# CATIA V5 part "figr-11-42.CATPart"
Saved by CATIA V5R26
Part number: Part1
Bounding box of the stored display mesh (mm): x -82.6 to 82.6, y -78 to 78, z 0 to 136
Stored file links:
  D:\_Deepak\CATIA\CATIA V5-6R2016_Deepak\Resources\Part files\Partfiles\c11_catia_v5_6r2016_prt\figr-11-42.CATPart
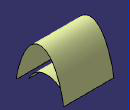
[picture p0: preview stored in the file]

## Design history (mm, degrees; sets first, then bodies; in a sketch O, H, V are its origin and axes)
Set1
  Extrude1: Element1 Sketch1, Lim1 59, Lim2 59, Direction yz-plane
  Affinity1: ToTransfor Extrude1, RatioX 1.4, RatioY 1.3, RatioZ 3.4
Body1 (main body)
  Sketch1 on yz-plane, origin (0, 0, 0), H (0, 1, 0), V (0, 0, 1)
    arc A1 centre (0, -25) radius 65 from (-60, 0) to (60, 0) cw
    point P2 (-60, 0)
    point P3 (60, 0)
    coincidence: P2 H, P3 H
